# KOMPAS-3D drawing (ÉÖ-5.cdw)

Referenced files: РЩ-5.cdw
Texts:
  Реконструкция элеткроснабжения помещений 2 го этажа  первой детской городской больницы
  Microsoft
  Текст на чертеже
  Размерные надписи
  Шероховатость
  Линия-выноска #1
  Линия-выноска #2
  Линия-выноска #3
  Отклонения формы и база
  Заголовок таблицы
  Ячейка таблицы
  Стрелка вида
  Обозначение изменения
  Фигурная скобка
  Номер узла
  Марка координационной оси
  VRCB
  Выносная надпись
  Обозначение узла
  Марка/позиционное обозначение с линией-выноской
  Марка/позиционное обозначение на линии
  Марка/позиционное обозначение без линии-выноски
  ВА 47-29 (1)
  ВА 47-29 (3)
  Номер группы
  Р кВт
  Ток, А
  Гр34
  Гр35
  Гр36
  Гр53
  Освещение
  ВВГ 5х4 мм 2  скрыто в ст.
  трубе от ВРУ
  ВВГнгLS 3х1,5 скрыто
  РЩ-5 (ЩРВ-24)
  Гр54
  Гр55
  Розетки
  АД12М
  ВВГнгLS 3х2,5 скрыто
  CONTINUOUS0
  Реконструкция элеткроснабжения помещений 2 го этажа
  первой детской городской больницы
  ГИП
  Разработ
  Однолинейная схема щита РЩ-5
Dimensions and other numbers on the sheet: 41/12-2009.ЭС; 7; 10А; 16А; 5.5; 1.0; 0.4; 1.8; 0.12; 0.36; 0.3; 0.5; 1.7; 1.4; 2.3; 16А Iсраб=30мА; 1:1; 5; 0; 1; 2; 3; 4; 6; 8; 9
